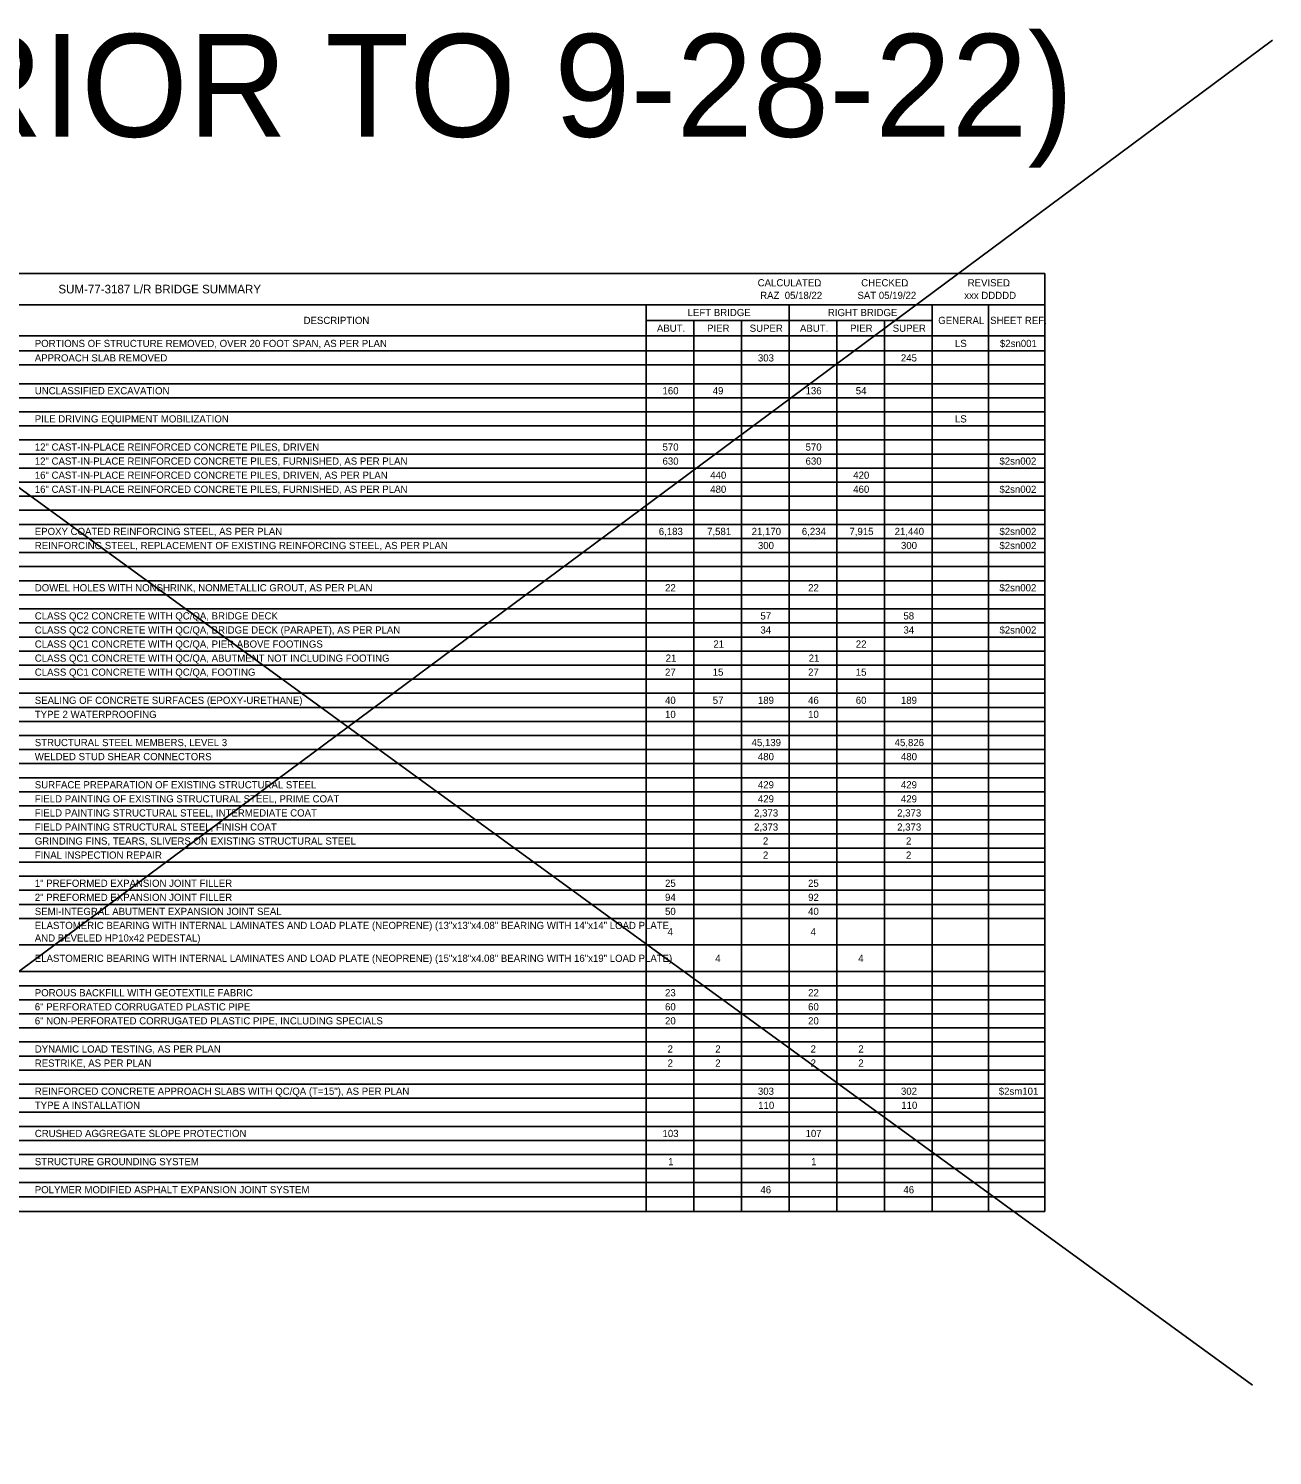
# Model space of a CAD drawing. Extents: x -62.6 to 33.3, y -2.9 to 24.9.
# Drawn here: x -49.74 to -25.52, y -2.88 to 24.89 of the extents above; entities that cross this region are included whole.
import ezdxf

# ---------------------------------------------------------------- set-up
doc = ezdxf.new("R2010")
doc.units = 0
doc.layers.add('Default', color=7, linetype='Continuous')
doc.layers.add('SH_Major_Grid_Line', color=7, linetype='Continuous')

msp = doc.modelspace()

# ---------------------------------------------------------------- linework, layer by layer
at = {"layer": 'Default'}
for p, q in [((-58.718, 20.126), (-29.957, 20.126)), ((-29.957, 20.126), (-29.957, 1.866)), ((-58.718, 19.518), (-29.957, 19.518)), ((-37.718, 19.518), (-37.718, 1.866)), ((-34.933, 19.518), (-34.933, 1.866)), ((-32.149, 19.518), (-32.149, 1.866)), ((-31.053, 19.518), (-31.053, 1.866)), ((-37.718, 19.213), (-32.149, 19.213)), ((-36.79, 19.213), (-36.79, 1.866)), ((-35.862, 19.213), (-35.862, 1.866)), ((-34.005, 19.213), (-34.005, 1.866)), ((-33.077, 19.213), (-33.077, 1.866)), ((-58.718, 18.909), (-29.957, 18.909)), ((-58.718, 18.62), (-29.957, 18.62)), ((-58.718, 18.346), (-29.957, 18.346)), ((-58.718, 17.981), (-29.957, 17.981)), ((-58.718, 17.707), (-29.957, 17.707)), ((-58.718, 17.433), (-29.957, 17.433)), ((-58.718, 17.159), (-29.957, 17.159)), ((-58.718, 16.885), (-29.957, 16.885)), ((-58.718, 16.611), (-29.957, 16.611)), ((-58.718, 16.337), (-29.957, 16.337)), ((-58.718, 16.063), (-29.957, 16.063)), ((-58.718, 15.789), (-29.957, 15.789)), ((-58.718, 15.516), (-29.957, 15.516)), ((-58.718, 15.242), (-29.957, 15.242)), ((-58.718, 14.968), (-29.957, 14.968)), ((-58.718, 14.694), (-29.957, 14.694)), ((-58.718, 14.42), (-29.957, 14.42)), ((-58.718, 14.146), (-29.957, 14.146)), ((-58.718, 13.872), (-29.957, 13.872)), ((-58.718, 13.598), (-29.957, 13.598)), ((-58.718, 13.324), (-29.957, 13.324)), ((-58.718, 13.05), (-29.957, 13.05)), ((-58.718, 12.776), (-29.957, 12.776)), ((-58.718, 12.502), (-29.957, 12.502)), ((-58.718, 12.229), (-29.957, 12.229)), ((-58.718, 11.955), (-29.957, 11.955)), ((-58.718, 11.681), (-29.957, 11.681)), ((-58.718, 11.407), (-29.957, 11.407)), ((-58.718, 11.133), (-29.957, 11.133)), ((-58.718, 10.859), (-29.957, 10.859)), ((-58.718, 10.585), (-29.957, 10.585)), ((-58.718, 10.311), (-29.957, 10.311)), ((-58.718, 10.037), (-29.957, 10.037)), ((-58.718, 9.763), (-29.957, 9.763)), ((-58.718, 9.489), (-29.957, 9.489)), ((-58.718, 9.216), (-29.957, 9.216)), ((-58.718, 8.942), (-29.957, 8.942)), ((-58.718, 8.668), (-29.957, 8.668)), ((-58.718, 8.394), (-29.957, 8.394)), ((-58.718, 8.12), (-29.957, 8.12)), ((-58.718, 7.846), (-29.957, 7.846)), ((-58.718, 7.572), (-29.957, 7.572)), ((-58.718, 7.055), (-29.957, 7.055)), ((-58.718, 6.537), (-29.957, 6.537)), ((-58.718, 6.263), (-29.957, 6.263)), ((-58.718, 5.989), (-29.957, 5.989)), ((-58.718, 5.716), (-29.957, 5.716)), ((-58.718, 5.442), (-29.957, 5.442)), ((-58.718, 5.168), (-29.957, 5.168)), ((-58.718, 4.894), (-29.957, 4.894)), ((-58.718, 4.62), (-29.957, 4.62)), ((-58.718, 4.346), (-29.957, 4.346)), ((-58.718, 4.072), (-29.957, 4.072)), ((-58.718, 3.798), (-29.957, 3.798)), ((-58.718, 3.524), (-29.957, 3.524)), ((-58.718, 3.25), (-29.957, 3.25)), ((-58.718, 2.976), (-29.957, 2.976)), ((-58.718, 2.702), (-29.957, 2.702)), ((-58.718, 2.429), (-29.957, 2.429)), ((-58.718, 2.155), (-29.957, 2.155)), ((-58.718, 1.866), (-29.957, 1.866))]:
    msp.add_line(p, q, dxfattribs=at)
at = {"layer": 'SH_Major_Grid_Line'}
for p, q in [((-25.522, 24.668), (-62.613, -2.881)), ((-61.637, 24.473), (-25.913, -1.513))]:
    msp.add_line(p, q, dxfattribs=at)

# ---------------------------------------------------------------- texts
for s, height, p in [('OLD (PRIOR TO 9-28-22)', 2, (-60.308, 22.787)), ('CALCULATED', 0.14, (-35.545, 19.875)), ('CHECKED', 0.14, (-33.529, 19.875)), ('REVISED', 0.14, (-31.456, 19.875)), ('SUM-77-3187 L/R BRIDGE SUMMARY', 0.168, (-49.158, 19.738)), ('RAZ  05/18/22', 0.14, (-35.496, 19.63)), (':', 0.14, (-34.355, 19.875)), ('SAT 05/19/22', 0.14, (-33.602, 19.63)), (': ', 0.14, (-32.658, 19.875)), ('xxx DDDDD', 0.14, (-31.523, 19.63)), (': ', 0.14, (-30.683, 19.875)), ('DESCRIPTION', 0.14, (-44.385, 19.143)), ('LEFT BRIDGE', 0.14, (-36.908, 19.296)), ('RIGHT BRIDGE', 0.14, (-34.177, 19.296)), ('GENERAL', 0.14, (-32.029, 19.143)), ('SHEET REF.', 0.14, (-31.018, 19.143)), ('ABUT.', 0.14, (-37.506, 18.991)), ('PIER', 0.14, (-36.53, 18.991)), ('SUPER', 0.14, (-35.7, 18.991)), ('ABUT.', 0.14, (-34.721, 18.991)), ('PIER', 0.14, (-33.745, 18.991)), ('SUPER', 0.14, (-32.915, 18.991)), ('PORTIONS OF STRUCTURE REMOVED, OVER 20 FOOT SPAN, AS PER PLAN', 0.14, (-49.618, 18.694)), ('LS', 0.14, (-31.704, 18.694)), ('$2sn001', 0.14, (-30.827, 18.694)), ('APPROACH SLAB REMOVED', 0.14, (-49.618, 18.413)), ('303', 0.14, (-35.54, 18.413)), ('245', 0.14, (-32.756, 18.413)), ('UNCLASSIFIED EXCAVATION', 0.14, (-49.618, 17.774)), ('160', 0.14, (-37.397, 17.774)), ('49', 0.14, (-36.42, 17.774)), ('136', 0.14, (-34.612, 17.774)), ('54', 0.14, (-33.635, 17.774)), ('PILE DRIVING EQUIPMENT MOBILIZATION', 0.14, (-49.618, 17.226)), ('LS', 0.14, (-31.704, 17.226)), ('12" CAST-IN-PLACE REINFORCED CONCRETE PILES, DRIVEN', 0.14, (-49.618, 16.678)), ('570', 0.14, (-37.397, 16.678)), ('570', 0.14, (-34.612, 16.678)), ('12" CAST-IN-PLACE REINFORCED CONCRETE PILES, FURNISHED, AS PER PLAN', 0.14, (-49.618, 16.404)), ('630', 0.14, (-37.397, 16.404)), ('630', 0.14, (-34.612, 16.404)), ('$2sn002', 0.14, (-30.838, 16.404)), ('16" CAST-IN-PLACE REINFORCED CONCRETE PILES, DRIVEN, AS PER PLAN', 0.14, (-49.618, 16.13)), ('440', 0.14, (-36.468, 16.13)), ('420', 0.14, (-33.684, 16.13)), ('16" CAST-IN-PLACE REINFORCED CONCRETE PILES, FURNISHED, AS PER PLAN', 0.14, (-49.618, 15.856)), ('480', 0.14, (-36.468, 15.856)), ('460', 0.14, (-33.684, 15.856)), ('$2sn002', 0.14, (-30.838, 15.856)), ('EPOXY COATED REINFORCING STEEL, AS PER PLAN', 0.14, (-49.618, 15.035)), ('6,183', 0.14, (-37.47, 15.035)), ('7,581', 0.14, (-36.53, 15.035)), ('21,170', 0.14, (-35.662, 15.035)), ('6,234', 0.14, (-34.685, 15.035)), ('7,915', 0.14, (-33.758, 15.035)), ('21,440', 0.14, (-32.878, 15.035)), ('$2sn002', 0.14, (-30.838, 15.035)), ('REINFORCING STEEL, REPLACEMENT OF EXISTING REINFORCING STEEL, AS PER PLAN', 0.14, (-49.618, 14.761)), ('300', 0.14, (-35.54, 14.761)), ('300', 0.14, (-32.755, 14.761)), ('$2sn002', 0.14, (-30.838, 14.761)), ('DOWEL HOLES WITH NONSHRINK, NONMETALLIC GROUT, AS PER PLAN', 0.14, (-49.618, 13.939)), ('22', 0.14, (-37.347, 13.939)), ('22', 0.14, (-34.562, 13.939)), ('$2sn002', 0.14, (-30.838, 13.939)), ('CLASS QC2 CONCRETE WITH QC/QA, BRIDGE DECK', 0.14, (-49.618, 13.391)), ('57', 0.14, (-35.491, 13.391)), ('58', 0.14, (-32.707, 13.391)), ('CLASS QC2 CONCRETE WITH QC/QA, BRIDGE DECK (PARAPET), AS PER PLAN', 0.14, (-49.618, 13.117)), ('34', 0.14, (-35.491, 13.117)), ('34', 0.14, (-32.706, 13.117)), ('$2sn002', 0.14, (-30.838, 13.117)), ('CLASS QC1 CONCRETE WITH QC/QA, PIER ABOVE FOOTINGS', 0.14, (-49.618, 12.843)), ('21', 0.14, (-36.407, 12.843)), ('22', 0.14, (-33.634, 12.843)), ('CLASS QC1 CONCRETE WITH QC/QA, ABUTMENT NOT INCLUDING FOOTING', 0.14, (-49.618, 12.569)), ('21', 0.14, (-37.336, 12.569)), ('21', 0.14, (-34.551, 12.569)), ('CLASS QC1 CONCRETE WITH QC/QA, FOOTING', 0.14, (-49.618, 12.296)), ('27', 0.14, (-37.348, 12.296)), ('15', 0.14, (-36.42, 12.296)), ('27', 0.14, (-34.563, 12.296)), ('15', 0.14, (-33.635, 12.296)), ('SEALING OF CONCRETE SURFACES (EPOXY-URETHANE)', 0.14, (-49.618, 11.748)), ('40', 0.14, (-37.348, 11.748)), ('57', 0.14, (-36.42, 11.748)), ('189', 0.14, (-35.54, 11.748)), ('46', 0.14, (-34.563, 11.748)), ('60', 0.14, (-33.635, 11.748)), ('189', 0.14, (-32.756, 11.748)), ('TYPE 2 WATERPROOFING', 0.14, (-49.618, 11.474)), ('10', 0.14, (-37.348, 11.474)), ('10', 0.14, (-34.563, 11.474)), ('STRUCTURAL STEEL MEMBERS, LEVEL 3', 0.14, (-49.618, 10.926)), ('45,139', 0.14, (-35.663, 10.926)), ('45,826', 0.14, (-32.878, 10.926)), ('WELDED STUD SHEAR CONNECTORS', 0.14, (-49.618, 10.652)), ('480', 0.14, (-35.54, 10.652)), ('480', 0.14, (-32.755, 10.652)), ('SURFACE PREPARATION OF EXISTING STRUCTURAL STEEL', 0.14, (-49.618, 10.104)), ('429', 0.14, (-35.54, 10.104)), ('429', 0.14, (-32.756, 10.104)), ('FIELD PAINTING OF EXISTING STRUCTURAL STEEL, PRIME COAT', 0.14, (-49.618, 9.83)), ('429', 0.14, (-35.54, 9.83)), ('429', 0.14, (-32.756, 9.83)), ('FIELD PAINTING STRUCTURAL STEEL, INTERMEDIATE COAT', 0.14, (-49.618, 9.556)), ('2,373', 0.14, (-35.614, 9.556)), ('2,373', 0.14, (-32.829, 9.556)), ('FIELD PAINTING STRUCTURAL STEEL, FINISH COAT', 0.14, (-49.618, 9.282)), ('2,373', 0.14, (-35.614, 9.282)), ('2,373', 0.14, (-32.829, 9.282)), ('GRINDING FINS, TEARS, SLIVERS ON EXISTING STRUCTURAL STEEL', 0.14, (-49.618, 9.009)), ('2', 0.14, (-35.442, 9.009)), ('2', 0.14, (-32.657, 9.009)), ('FINAL INSPECTION REPAIR', 0.14, (-49.618, 8.735)), ('2', 0.14, (-35.442, 8.735)), ('2', 0.14, (-32.657, 8.735)), ('2" PREFORMED EXPANSION JOINT FILLER', 0.14, (-49.618, 7.913)), ('1" PREFORMED EXPANSION JOINT FILLER', 0.14, (-49.618, 8.187)), ('25', 0.14, (-37.348, 8.187)), ('94', 0.14, (-37.348, 7.913)), ('25', 0.14, (-34.564, 8.187)), ('92', 0.14, (-34.562, 7.913)), ('SEMI-INTEGRAL ABUTMENT EXPANSION JOINT SEAL', 0.14, (-49.618, 7.639)), ('50', 0.14, (-37.348, 7.639)), ('40', 0.14, (-34.563, 7.639)), ('ELASTOMERIC BEARING WITH INTERNAL LAMINATES AND LOAD PLATE (NEOPRENE) (13"x13"x4.08" BEARING WITH 14"x14" LOAD PLATE ', 0.14, (-49.618, 7.366)), ('AND BEVELED HP10x42 PEDESTAL)', 0.14, (-49.618, 7.121)), ('4', 0.14, (-37.299, 7.243)), ('4', 0.14, (-34.514, 7.243)), ('ELASTOMERIC BEARING WITH INTERNAL LAMINATES AND LOAD PLATE (NEOPRENE) (15"x18"x4.08" BEARING WITH 16"x19" LOAD PLATE)', 0.14, (-49.618, 6.726)), ('4', 0.14, (-36.37, 6.726)), ('4', 0.14, (-33.586, 6.726)), ('POROUS BACKFILL WITH GEOTEXTILE FABRIC', 0.14, (-49.618, 6.056)), ('23', 0.14, (-37.348, 6.056)), ('22', 0.14, (-34.562, 6.056)), ('6" PERFORATED CORRUGATED PLASTIC PIPE', 0.14, (-49.618, 5.782)), ('60', 0.14, (-37.348, 5.782)), ('60', 0.14, (-34.563, 5.782)), ('6" NON-PERFORATED CORRUGATED PLASTIC PIPE, INCLUDING SPECIALS', 0.14, (-49.618, 5.509)), ('20', 0.14, (-37.348, 5.509)), ('20', 0.14, (-34.563, 5.509)), ('DYNAMIC LOAD TESTING, AS PER PLAN', 0.14, (-49.618, 4.961)), ('2', 0.14, (-37.298, 4.961)), ('2', 0.14, (-36.37, 4.961)), ('2', 0.14, (-34.514, 4.961)), ('2', 0.14, (-33.585, 4.961)), ('RESTRIKE, AS PER PLAN', 0.14, (-49.618, 4.687)), ('2', 0.14, (-37.298, 4.687)), ('2', 0.14, (-36.37, 4.687)), ('2', 0.14, (-34.514, 4.687)), ('2', 0.14, (-33.585, 4.687)), ('REINFORCED CONCRETE APPROACH SLABS WITH QC/QA (T=15"), AS PER PLAN', 0.14, (-49.618, 4.139)), ('303', 0.14, (-35.54, 4.139)), ('302', 0.14, (-32.755, 4.139)), ('$2sm101', 0.14, (-30.851, 4.139)), ('TYPE A INSTALLATION', 0.14, (-49.618, 3.865)), ('110', 0.14, (-35.534, 3.865)), ('110', 0.14, (-32.749, 3.865)), ('CRUSHED AGGREGATE SLOPE PROTECTION', 0.14, (-49.618, 3.317)), ('103', 0.14, (-37.397, 3.317)), ('107', 0.14, (-34.612, 3.317)), ('STRUCTURE GROUNDING SYSTEM', 0.14, (-49.618, 2.769)), ('1', 0.14, (-37.287, 2.769)), ('1', 0.14, (-34.502, 2.769)), ('POLYMER MODIFIED ASPHALT EXPANSION JOINT SYSTEM', 0.14, (-49.618, 2.222)), ('46', 0.14, (-35.491, 2.222)), ('46', 0.14, (-32.707, 2.222))]:
    msp.add_text(s, height=height, dxfattribs=at).set_placement(p)

doc.saveas('drawing.dxf')
